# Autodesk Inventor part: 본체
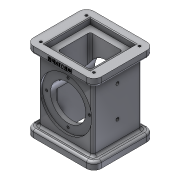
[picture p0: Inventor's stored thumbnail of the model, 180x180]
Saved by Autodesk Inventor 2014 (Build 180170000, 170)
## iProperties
Created: 2017-08
Part Number: 본체
Material: Aluminum 6061
Document SubType Name: Modeling
Designer: user
Density: 2.71 g/cm^3
Appearance: Aluminum - Flat
Mass: 810.055 g
Surface Area: 619.348 cm^2
Volume: 298.913 cm^3
Author: user
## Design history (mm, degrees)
sketch "Sketch1"
  geometry: L1 (-46, 41)-(46, 41); L2 (46, 41)-(46, -41); L3 (46, -41)-(-46, -41); L4 (-46, -41)-(-46, 41); L5 (-46, 41)-(46, -41); L6 (46, 41)-(-46, -41); 1 further point
  constraints: 12 end point, 2 midpoint, 2 parallel, 1 horizontal, 1 perpendicular
  dimensions: "d0" = 92 distance of L1.start L1.end; "d1" = 82 distance of L1.end L2.end
extrude "Extrusion1" new body sketch "Sketch1" distance "d2" = 10; taper "d3" = 0 deg
sketch "Sketch2"
  geometry: L1 (-37, 33)-(37, 33); L2 (37, 33)-(37, -33); L3 (37, -33)-(-37, -33); L4 (-37, -33)-(-37, 33); L5 (-37, 33)-(37, -33); L6 (37, 33)-(-37, -33); 1 further point
  constraints: 12 end point, 2 midpoint, 2 parallel, 1 horizontal, 1 perpendicular
  dimensions: "d12" = 74 distance of L2.end L3.end; "d13" = 66 distance of L1.end L2.end
extrude "Extrusion2" join sketch "Sketch2" distance "d5" = 88; taper "d6" = 0 deg
sketch "Sketch3"
  geometry: L1 (-46, 41)-(46, 41); L2 (46, 41)-(46, -41); L3 (46, -41)-(-46, -41); L4 (-46, -41)-(-46, 41); L5 (-46, 41)-(46, -41); L6 (46, 41)-(-46, -41); 1 further point
  constraints: 12 end point, 2 midpoint, 2 parallel, 1 horizontal, 1 perpendicular
  dimensions: "d7" = 82 distance of L1.end L2.end; "d8" = 92 distance of L2.end L3.end
extrude "Extrusion3" join sketch "Sketch3" distance "d9" = 10; taper "d10" = 0 deg
sketch "Sketch4"
  geometry: L1 (-22, 22)-(22, 22); L2 (22, 22)-(22, -22); L3 (22, -22)-(-22, -22); L4 (-22, -22)-(-22, 22); L5 (-22, 22)-(22, -22); L6 (22, 22)-(-22, -22); 1 further point
  constraints: 12 end point, 2 midpoint, 2 parallel, 1 horizontal, 1 perpendicular
  dimensions: "d14" = 44 distance of L2.end L3.end; "d15" = 44 distance of L1.end L2.end
extrude "Extrusion4" cut sketch "Sketch4" stored distance "d16" = 10; taper "d17" = 0 deg
sketch "Sketch6"
  geometry: L1 (83, -10)-(-9, -10) reference; C1 r 24 at (37, 44); 2 further points
  constraints: 1 centre point, 1 midpoint, 1 vertical alignment
  dimensions: "d18" = 48 diameter of C1; "d19" = 54 distance from line of L1 C1.centre
extrude "Extrusion5" cut sketch "Sketch6" stored distance "d20" = 10; taper "d21" = 0 deg
sketch "Sketch7"
  geometry: L1 (-24, 24)-(24, 24); L2 (24, 24)-(24, -24); L3 (24, -24)-(-24, -24); L4 (-24, -24)-(-24, 24); L5 (-24, 24)-(24, -24); L6 (24, 24)-(-24, -24); 1 further point
  constraints: 12 end point, 2 midpoint, 2 parallel, 1 horizontal, 1 perpendicular
  dimensions: "d22" = 48 distance of L2.end L3.end; "d23" = 48 distance of L1.end L2.end
extrude "Extrusion6" cut sketch "Sketch7" stored distance "d24" = 10; taper "d25" = 0 deg
sketch "Sketch8"
  geometry: C1 r 24 at (37, 44) reference; C2 r 35 at (37, 44); 1 further point
  constraints: 1 centre point, 1 coincident
  dimensions: "d26" = 70 diameter of C2
extrude "Extrusion7" cut sketch "Sketch8" distance "d27" = 3; taper "d28" = 0 deg
mirror "Mirror1"
sketch "Sketch9"
  geometry: L1 (0, 0)-(0, 29); C1 r 35 at (0, 0) reference; 1 further point
  constraints: 2 end point, 1 vertical
  dimensions: "d29" = 29 distance of L1.start L1.end
hole "Hole1" sketch "Sketch9" at (0, 29) diameter "d30" = 3.242; stored, may be unused: countersink angle "d34" = 90 deg, drill point angle "d36" = 118 deg; dims "d31" = 4, "d32" = 4, "d33" = 2, "d35" = 6
pattern_circular "Circular Pattern1" dims angle "d38" = 360 deg
mirror "Mirror2"
sketch "Sketch10"
  geometry: L1 (-36, 31)-(36, 31); L2 (36, 31)-(36, -31); L3 (36, -31)-(-36, -31); L4 (-36, -31)-(-36, 31); L5 (-36, 31)-(36, -31); L6 (36, 31)-(-36, -31); 2 further points
  constraints: 12 end point, 2 midpoint, 2 parallel, 1 coincident, 1 horizontal, 1 perpendicular
  dimensions: "d40" = 62 distance of L1.end L2.end; "d41" = 72 distance of L1.start L1.end
hole "Hole2" sketch "Sketch10" at (36, -31) diameter "d42" = 3.242; stored, may be unused: countersink angle "d46" = 90 deg, drill point angle "d48" = 118 deg; dims "d43" = 4, "d44" = 4, "d45" = 2, "d47" = 6
mirror "Mirror3"
mirror "Mirror4"
sketch "Sketch11"
  geometry: L1 (-36, 31)-(36, 31); L2 (36, 31)-(36, -31); L3 (36, -31)-(-36, -31); L4 (-36, -31)-(-36, 31); L5 (-36, 31)-(36, -31); L6 (36, 31)-(-36, -31); 2 further points
  constraints: 12 end point, 2 midpoint, 2 parallel, 1 coincident, 1 horizontal, 1 perpendicular
  dimensions: "d49" = 62 distance of L1.end L2.end; "d50" = 72 distance of L1.start L1.end
hole "Hole3" sketch "Sketch11" at (36, -31) diameter "d51" = 3.242; stored, may be unused: countersink angle "d55" = 90 deg, drill point angle "d57" = 118 deg; dims "d52" = 4, "d53" = 4, "d54" = 2, "d56" = 6
mirror "Mirror5"
mirror "Mirror6"
fillet "Fillet1" dims "d58" = 10
fillet "Fillet2" dims "d59" = 3
fillet "Fillet3" dims "d60" = 3
fillet "Fillet4" dims "d61" = 3
fillet "Fillet5" dims "d62" = 3
sketch "Sketch12"
  geometry: L1 (61, -13)-(-1, -13) reference; 5 further points
  constraints: 2 midpoint, 2 vertical alignment
  dimensions: "d63" = 38 distance from line of point (30, 25) L1; "d64" = 42 distance of point (30, 67) point (30, 25)
hole "Hole4" sketch "Sketch12" at (30, 25), (30, 67) diameter "d65" = 4.134; stored, may be unused: countersink angle "d69" = 90 deg, drill point angle "d71" = 0 deg; dims "d66" = 4, "d67" = 4, "d68" = 2, "d70" = 6
sketch "Sketch13"
  geometry: L1 (-10, 0)-(-10, -7) reference; L2 (72, 0)-(82, 0) reference; 2 further points
  constraints: 1 other
  dimensions: "d72" = 46 distance from line of point (36, -4) L1; "d73" = 4 distance from line of point (36, -4) L2
emboss "Emboss1" sketch "Sketch13" dims "d0" = 92, "d1" = 82, "d74" = 0.5, "d75" = 0
chamfer "Chamfer1" distance "d76" = 1; stored, may be unused: second distance "d77" = 2, angle "d78" = 45 deg
sketch "Sketch14"
  geometry: L1 (-31, 31)-(31, 31); L2 (31, 31)-(31, -31); L3 (31, -31)-(-31, -31); L4 (-31, -31)-(-31, 31); L5 (-31, 31)-(31, -31); L6 (31, 31)-(-31, -31); 1 further point
  constraints: 12 end point, 2 midpoint, 2 parallel, 1 horizontal, 1 perpendicular
  dimensions: "d79" = 62 distance of L1.end L2.end; "d80" = 62 distance of L2.end L3.end
extrude "Extrusion8" cut sketch "Sketch14" distance "d81" = 8; taper "d82" = 0 deg
chamfer "Chamfer2" distance "d83" = 1; stored, may be unused: second distance "d84" = 2, angle "d85" = 45 deg
body "Solid1"
